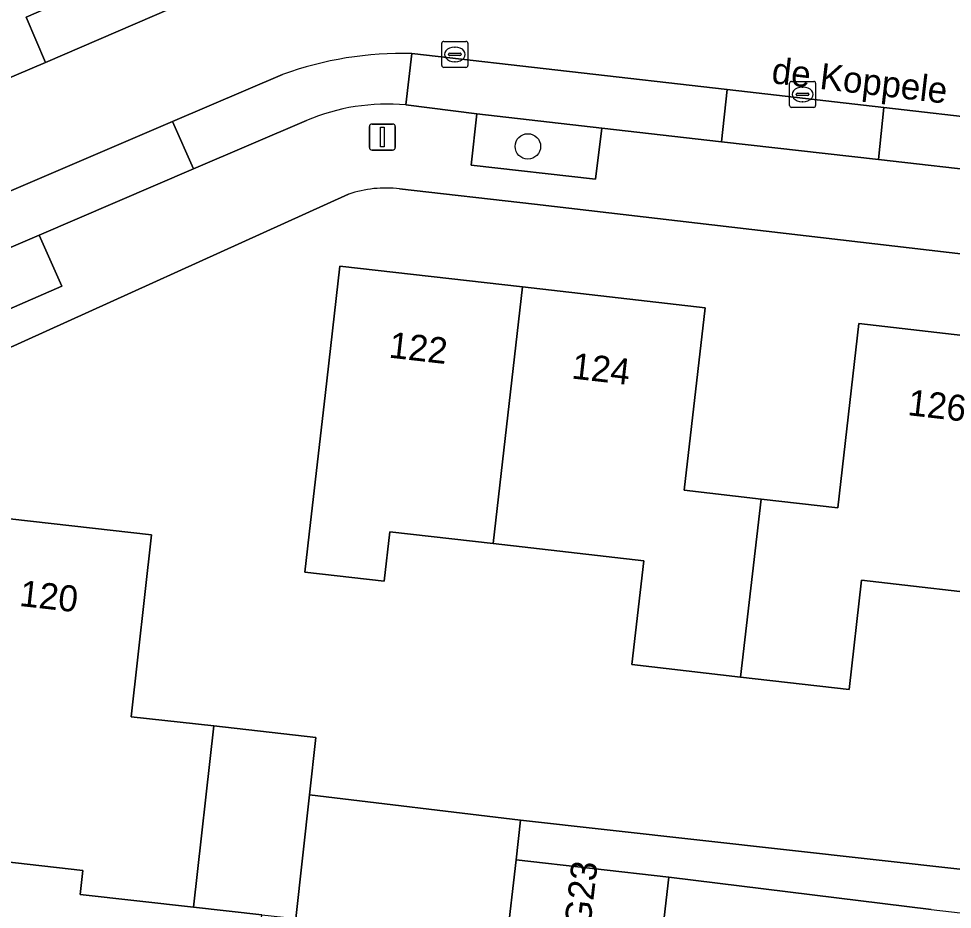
# Model space of a CAD drawing. Extents: x 162026 to 163502, y 387295 to 388169.
# Drawn here: x 162241.43 to 162277.28, y 387953.87 to 387988.1 of the extents above; entities that cross this region are included whole.
import ezdxf

# ---------------------------------------------------------------- set-up
doc = ezdxf.new("R2010")
doc.units = 0
for name, color, linetype in [('IMGEO_Boom', 7, 'Continuous'), ('IMGEO_Erf', 7, 'Continuous'), ('IMGEO_Groenvoorziening', 7, 'Continuous'), ('IMGEO_Kolk', 7, 'Continuous'), ('IMGEO_Lichtmast', 7, 'Continuous'), ('IMGEO_Openbare_ruimte_label', 7, 'Continuous'), ('IMGEO_Pand', 7, 'Continuous'), ('IMGEO_Pand_nummerreeks', 7, 'Continuous'), ('IMGEO_Parkeervlak_open', 7, 'Continuous'), ('IMGEO_Rijbaan_lokaal_open', 7, 'Continuous'), ('IMGEO_Voetpad_open', 7, 'Continuous')]:
    doc.layers.add(name, color=color, linetype=linetype)

msp = doc.modelspace()

# ---------------------------------------------------------------- linework, layer by layer
at = {"layer": 'IMGEO_Boom'}
msp.add_circle((162260.982, 387983.187), 0.489, dxfattribs=at)
at = {"layer": 'IMGEO_Erf'}
for points in [[(162254.101, 387981.349), (162240.014, 387974.97), (162211.554, 387962.659)], [(162291.097, 387977.515), (162290.634, 387977.587), (162288.142, 387977.833), (162261.241, 387980.973), (162256.056, 387981.553)], [(162279.564, 387965.862), (162273.794, 387966.523), (162273.313, 387962.322), (162269.152, 387962.798), (162264.977, 387963.276), (162265.434, 387967.268), (162259.65, 387967.93), (162255.684, 387968.384), (162255.467, 387966.486), (162252.418, 387966.835), (162252.635, 387968.733), (162253.195, 387973.623), (162253.763, 387978.59), (162260.778, 387977.787), (162267.788, 387976.985), (162266.985, 387969.975), (162269.935, 387969.637), (162272.883, 387969.3), (162273.693, 387976.378), (162280.678, 387975.578)], [(162239.605, 387969.039), (162246.536, 387968.264), (162245.755, 387961.273), (162248.918, 387960.92), (162252.845, 387960.481), (162252.599, 387958.276), (162260.704, 387957.306), (162291.341, 387953.887), (162293.685, 387974.891)], [(162230.797, 387942.603), (162245.241, 387940.89), (162249.184, 387940.423), (162249.731, 387944.997), (162250.767, 387953.668), (162248.141, 387953.962), (162243.787, 387954.448), (162243.891, 387955.373), (162238.149, 387956.015)], [(162276.462, 387953.862), (162266.39, 387955.112), (162266.027, 387951.901)]]:
    msp.add_lwpolyline(points, dxfattribs=at)
msp.add_arc((162255.512, 387977.3), 4.287, 82.7049, 109.2094, dxfattribs=at)
at = {"layer": 'IMGEO_Groenvoorziening'}
msp.add_lwpolyline([(162246.195, 387990.109), (162241.722, 387988.158), (162242.466, 387986.409), (162247.956, 387988.784)], dxfattribs=at)
for points in [[(162263.824, 387983.889), (162259.028, 387984.445), (162258.806, 387982.466), (162263.585, 387981.924)], [(162242.216, 387979.783), (162237.792, 387977.882), (162238.653, 387975.881), (162243.088, 387977.819)]]:
    msp.add_lwpolyline(points, close=True, dxfattribs=at)
at = {"layer": 'IMGEO_Kolk'}
for p, q in [((162257.678, 387986.296), (162257.678, 387987.148)), ((162257.753, 387987.222), (162258.605, 387987.222)), ((162258.166, 387987.002), (162258.191, 387987.002)), ((162258.679, 387987.148), (162258.679, 387986.296)), ((162257.937, 387986.716), (162257.937, 387986.728)), ((162258.375, 387986.679), (162257.977, 387986.679)), ((162257.98, 387986.765), (162258.378, 387986.765)), ((162258.421, 387986.728), (162258.421, 387986.716)), ((162258.189, 387986.442), (162258.164, 387986.442)), ((162258.605, 387986.222), (162257.753, 387986.222)), ((162271.03, 387984.759), (162271.03, 387985.611)), ((162271.105, 387985.685), (162271.957, 387985.685)), ((162272.031, 387985.611), (162272.031, 387984.759)), ((162271.289, 387985.179), (162271.289, 387985.191)), ((162271.332, 387985.228), (162271.73, 387985.228)), ((162271.518, 387985.465), (162271.543, 387985.465)), ((162271.773, 387985.191), (162271.773, 387985.179)), ((162271.727, 387985.142), (162271.329, 387985.142)), ((162271.541, 387984.905), (162271.516, 387984.905)), ((162271.957, 387984.685), (162271.105, 387984.685))]:
    msp.add_line(p, q, dxfattribs=at)
for points in [[(162257.678, 387986.296), (162257.678, 387987.148)], [(162257.753, 387987.222), (162258.605, 387987.222)], [(162258.679, 387987.148), (162258.679, 387986.296)], [(162258.605, 387986.222), (162257.753, 387986.222)], [(162271.03, 387984.759), (162271.03, 387985.611)], [(162271.105, 387985.685), (162271.957, 387985.685)], [(162272.031, 387985.611), (162272.031, 387984.759)], [(162271.957, 387984.685), (162271.105, 387984.685)]]:
    msp.add_lwpolyline(points, dxfattribs=at)
for centre, radius, start, end in [((162257.755, 387987.146), 0.0765, 91.552, 178.448), ((162257.755, 387987.146), 0.0765, 91.552, 178.448), ((162258.603, 387987.146), 0.0765, 1.552, 88.448), ((162258.603, 387987.146), 0.0765, 1.552, 88.448), ((162257.977, 387986.725), 0.0403, 85.8775, 175.7526), ((162257.974, 387986.715), 0.0366, 178.938, 274.7102), ((162258.378, 387986.722), 0.043, 264.8664, 352.4533), ((162258.382, 387986.727), 0.0386, 1.7309, 96.639), ((162257.755, 387986.298), 0.0765, 181.552, 268.448), ((162257.755, 387986.298), 0.0765, 181.552, 268.448), ((162258.603, 387986.298), 0.0765, 271.552, 358.448), ((162258.603, 387986.298), 0.0765, 271.552, 358.448), ((162271.107, 387985.609), 0.0765, 91.552, 178.448), ((162271.107, 387985.609), 0.0765, 91.552, 178.448), ((162271.955, 387985.609), 0.0765, 1.552, 88.448), ((162271.955, 387985.609), 0.0765, 1.552, 88.448), ((162271.329, 387985.188), 0.0403, 85.8775, 175.7526), ((162271.326, 387985.178), 0.0366, 178.938, 274.7102), ((162271.73, 387985.185), 0.043, 264.8664, 352.4533), ((162271.734, 387985.19), 0.0386, 1.7309, 96.639), ((162271.107, 387984.761), 0.0765, 181.552, 268.448), ((162271.107, 387984.761), 0.0765, 181.552, 268.448), ((162271.955, 387984.761), 0.0765, 271.552, 358.448), ((162271.955, 387984.761), 0.0765, 271.552, 358.448)]:
    msp.add_arc(centre, radius, start, end, dxfattribs=at)
for centre, major_axis, ratio, start_param, end_param in [((162258.165, 387986.722), (-0.387, 0.002), 0.722429, 4.712389, 7.853982), ((162258.19, 387986.722), (-0.39, 0.002), 0.717154, 1.570796, 4.712389), ((162271.517, 387985.185), (-0.387, 0.002), 0.722429, 4.712389, 7.853982), ((162271.542, 387985.185), (-0.39, 0.002), 0.717154, 1.570796, 4.712389)]:
    msp.add_ellipse(centre, major_axis=major_axis, ratio=ratio, start_param=start_param, end_param=end_param, dxfattribs=at)
at = {"layer": 'IMGEO_Lichtmast'}
for p, q in [((162254.899, 387983.148), (162254.899, 387983.948)), ((162254.899, 387983.948), (162254.899, 387983.148)), ((162254.999, 387984.048), (162255.789, 387984.048)), ((162255.789, 387984.048), (162254.999, 387984.048)), ((162255.889, 387983.948), (162255.889, 387983.148)), ((162255.889, 387983.148), (162255.889, 387983.948)), ((162255.789, 387983.048), (162254.999, 387983.048)), ((162254.999, 387983.048), (162255.789, 387983.048))]:
    msp.add_line(p, q, dxfattribs=at)
msp.add_lwpolyline([(162255.319, 387983.923), (162255.469, 387983.923), (162255.469, 387983.173), (162255.319, 387983.173), (162255.319, 387983.923)], dxfattribs=at)
for centre, start, end in [((162254.999, 387983.948), 90, 180), ((162254.999, 387983.948), 90, 180), ((162255.789, 387983.948), 0, 90), ((162255.789, 387983.948), 360, 90), ((162254.999, 387983.148), 180, 270), ((162254.999, 387983.148), 180, 270), ((162255.789, 387983.148), 270, 0), ((162255.789, 387983.148), 270, 0)]:
    msp.add_arc(centre, 0.1, start, end, dxfattribs=at)
at = {"layer": 'IMGEO_Pand'}
for points in [[(162260.778, 387977.787), (162253.763, 387978.59), (162253.195, 387973.623), (162252.635, 387968.733), (162252.418, 387966.835), (162255.467, 387966.486), (162255.684, 387968.384), (162259.65, 387967.93)], [(162269.935, 387969.637), (162266.985, 387969.975), (162267.788, 387976.985), (162260.778, 387977.787), (162259.65, 387967.93), (162265.434, 387967.268), (162264.977, 387963.276), (162269.152, 387962.798)], [(162280.678, 387975.578), (162273.693, 387976.378), (162272.883, 387969.3), (162269.935, 387969.637), (162269.152, 387962.798), (162273.313, 387962.322), (162273.794, 387966.523), (162279.564, 387965.862)], [(162248.141, 387953.962), (162248.918, 387960.92), (162245.755, 387961.273), (162246.536, 387968.264), (162239.605, 387969.039), (162238.482, 387958.996), (162238.149, 387956.015), (162243.891, 387955.373), (162243.787, 387954.448)], [(162250.767, 387953.668), (162252.068, 387953.523), (162252.599, 387958.276), (162252.845, 387960.481), (162248.918, 387960.92), (162248.141, 387953.962)], [(162260.159, 387952.575), (162266.027, 387951.901), (162266.39, 387955.112), (162260.527, 387955.775)]]:
    msp.add_lwpolyline(points, close=True, dxfattribs=at)
at = {"layer": 'IMGEO_Parkeervlak_open'}
for points in [[(162256.533, 387986.755), (162256.295, 387984.784), (162259.028, 387984.445), (162263.824, 387983.889), (162268.419, 387983.366), (162268.637, 387985.369)], [(162287.36, 387983.225), (162274.652, 387984.68), (162274.447, 387982.68), (162278.942, 387982.168), (162282.345, 387981.742), (162283.404, 387981.609), (162285.117, 387981.352), (162287.087, 387980.885)], [(162248.138, 387982.33), (162247.34, 387984.14), (162231.087, 387977.179), (162231.849, 387975.337), (162237.792, 387977.882), (162242.216, 387979.783)]]:
    msp.add_lwpolyline(points, close=True, dxfattribs=at)
at = {"layer": 'IMGEO_Rijbaan_lokaal_open'}
for points in [[(162256.533, 387986.755), (162268.637, 387985.369), (162274.652, 387984.68), (162287.36, 387983.225), (162287.971, 387987.874), (162285.183, 387988.176), (162261.021, 387990.93)], [(162247.956, 387988.784), (162242.466, 387986.409), (162238.329, 387984.653), (162222.983, 387978.072), (162216.634, 387975.343), (162203.22, 387969.54)], [(162256.295, 387984.784), (162256.533, 387986.755)], [(162251.567, 387985.946), (162247.34, 387984.14), (162248.138, 387982.33), (162252.483, 387984.187)], [(162247.34, 387984.14), (162251.567, 387985.946)], [(162207.831, 387967.208), (162224.442, 387974.33), (162231.087, 387977.179), (162247.34, 387984.14)], [(162260.159, 387952.575), (162260.527, 387955.775), (162260.704, 387957.306), (162252.599, 387958.276), (162252.068, 387953.523)]]:
    msp.add_lwpolyline(points, dxfattribs=at)
msp.add_lwpolyline([(162274.652, 387984.68), (162268.637, 387985.369), (162268.419, 387983.366), (162274.447, 387982.68)], close=True, dxfattribs=at)
for centre, radius, start, end in [((162256.155, 387973.427), 13.333, 88.3765, 110.1288), ((162256.155, 387973.427), 13.333, 88.3765, 110.1288), ((162255.598, 387976.763), 8.051, 85.037, 112.7647)]:
    msp.add_arc(centre, radius, start, end, dxfattribs=at)
at = {"layer": 'IMGEO_Voetpad_open'}
for points in [[(162237.562, 387986.4), (162238.329, 387984.653), (162242.466, 387986.409), (162241.722, 387988.158), (162246.195, 387990.109)], [(162293.685, 387974.891), (162294.331, 387980.045), (162287.244, 387980.867), (162287.087, 387980.885), (162285.117, 387981.352), (162283.404, 387981.609), (162282.345, 387981.742), (162282.19, 387979.834), (162278.769, 387980.18), (162278.868, 387981.798), (162278.942, 387982.168), (162274.447, 387982.68), (162268.419, 387983.366), (162263.824, 387983.889), (162263.585, 387981.924), (162258.806, 387982.466), (162259.028, 387984.445), (162256.295, 387984.784)], [(162252.483, 387984.187), (162248.138, 387982.33), (162242.216, 387979.783), (162243.088, 387977.819), (162238.653, 387975.881), (162237.792, 387977.882), (162231.849, 387975.337), (162225.236, 387972.502), (162221.195, 387970.769), (162222.039, 387968.759), (162217.641, 387966.886), (162216.765, 387968.87), (162208.58, 387965.361), (162209.247, 387963.572)], [(162240.014, 387974.97), (162254.101, 387981.349)], [(162256.056, 387981.553), (162261.241, 387980.973), (162288.142, 387977.833), (162290.634, 387977.587), (162291.097, 387977.515)]]:
    msp.add_lwpolyline(points, dxfattribs=at)
msp.add_lwpolyline([(162260.704, 387957.306), (162260.527, 387955.775), (162266.39, 387955.112), (162276.462, 387953.862), (162285.289, 387952.859), (162291.153, 387952.205), (162291.341, 387953.887)], close=True, dxfattribs=at)
for centre, radius, start, end in [((162255.598, 387976.763), 8.051, 85.037, 112.7647), ((162255.512, 387977.3), 4.287, 82.7049, 109.2094)]:
    msp.add_arc(centre, radius, start, end, dxfattribs=at)

# ---------------------------------------------------------------- texts
at = {"layer": 'IMGEO_Openbare_ruimte_label'}
msp.add_text('de Koppele', height=1, rotation=353.2801, dxfattribs=at).set_placement((162270.308, 387985.62))
at = {"layer": 'IMGEO_Pand_nummerreeks'}
for s, rotation, p in [('122', 353.474, (162255.615, 387975.077)), ('124', 353.4716, (162262.63, 387974.274)), ('126', 353.4694, (162275.533, 387972.866)), ('120', 353.6235, (162241.431, 387965.534)), ('112/G23', 83.3752, (162263.073, 387950.569))]:
    msp.add_text(s, height=1, rotation=rotation, dxfattribs=at).set_placement(p)

doc.saveas('drawing.dxf')
